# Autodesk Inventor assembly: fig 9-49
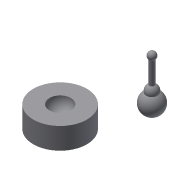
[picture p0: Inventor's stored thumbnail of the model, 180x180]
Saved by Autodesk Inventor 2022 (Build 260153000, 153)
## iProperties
Created: 2013-07
Part Number: fig 9-49
Document SubType Name: Assembly
Designer: CADCIM
Author: CADCIM
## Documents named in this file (3)
- D:\PROJECTS_2021\Resources\Part Files\c09_Inv_2022_prt\fig 9-50.iam
- D:\PROJECTS_2021\Resources\Part Files\c09_Inv_2022_prt\19.ipt
- D:\PROJECTS_2021\Resources\Part Files\c09_Inv_2022_prt\20.ipt
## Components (2 placed, 2 different names)
1. 19:1
2. 20:2
